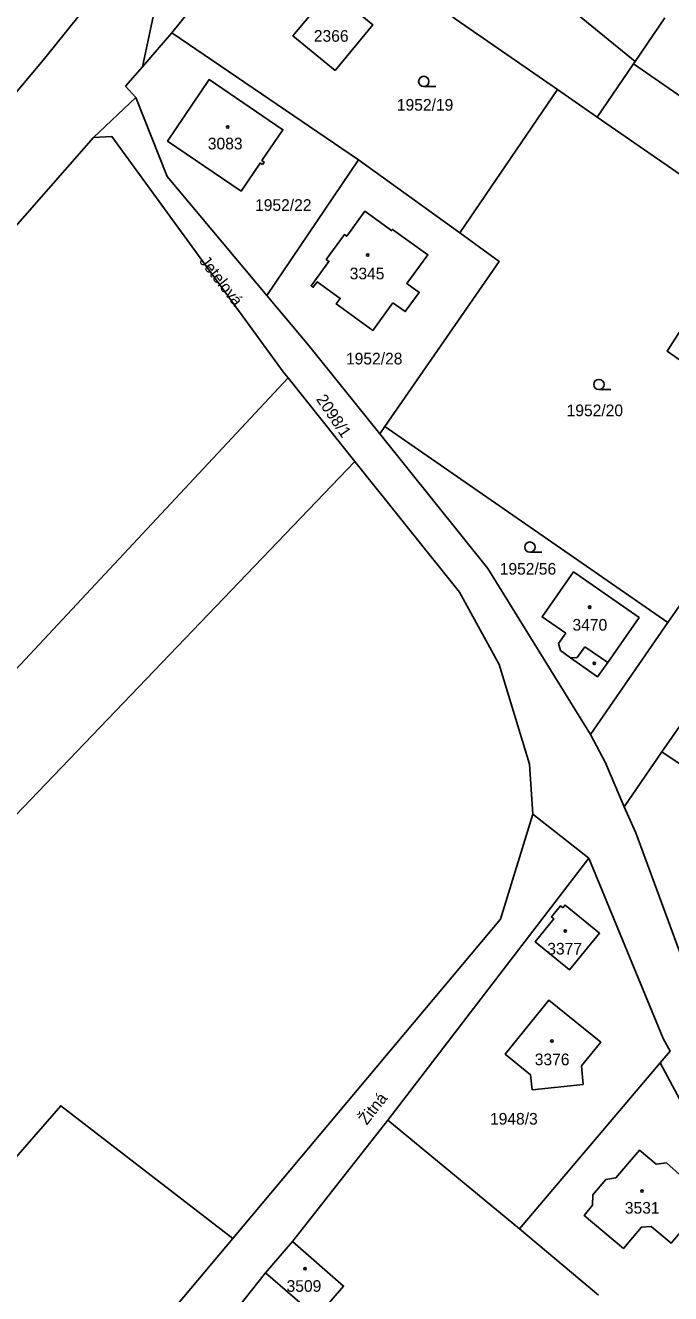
# Model space of a CAD drawing. Extents: x -679220 to -673243, y -1075091 to -1066557.
# Drawn here: x -676761.5 to -676667.6, y -1072885.5 to -1072700.8 of the extents above; entities that cross this region are included whole.
import ezdxf

# ---------------------------------------------------------------- set-up
doc = ezdxf.new("R2010")
doc.units = 0
for name, color, linetype in [('Hranice parcel', 7, 'Continuous'), ('Parcelní čísla', 7, 'Continuous'), ('Pop  PČ popisy', 7, 'Continuous'), ('Vnitřní kresba', 7, 'Continuous'), ('Značky budov', 7, 'Continuous'), ('Značky kultur', 7, 'Continuous')]:
    doc.layers.add(name, color=color, linetype=linetype)

msp = doc.modelspace()

# ---------------------------------------------------------------- linework, layer by layer
at = {"layer": 'Hranice parcel'}
for p, q in [((-676722.71, -1072680.24), (-676740.22, -1072701.84)), ((-676672.74, -1072706.03), (-676701.16, -1072682.79)), ((-676668.42, -1072699.67), (-676672.74, -1072706.03)), ((-676740.22, -1072701.84), (-676744.49, -1072706.81)), ((-676740.22, -1072701.84), (-676713, -1072720.34)), ((-676672.99, -1072706.39), (-676678.27, -1072714.14)), ((-676672.74, -1072706.03), (-676672.99, -1072706.39)), ((-676672.99, -1072706.39), (-676631.54, -1072735.13)), ((-676698.26, -1072731.01), (-676684.06, -1072710.13)), ((-676684.06, -1072710.13), (-676678.27, -1072714.14)), ((-676751.59, -1072717.1), (-676745.46, -1072711.26)), ((-676678.27, -1072714.14), (-676636.86, -1072742.81)), ((-676726.35, -1072740.11), (-676713, -1072720.34)), ((-676713, -1072720.34), (-676698.26, -1072731.01)), ((-676667.95, -1072787.75), (-676636.86, -1072742.81)), ((-676804.41, -1072838.99), (-676723.28, -1072752.14)), ((-676723.28, -1072752.14), (-676713.57, -1072764.29)), ((-676709.92, -1072760.26), (-676709.2, -1072759.21)), ((-676651.64, -1072781.8), (-676668.84, -1072806.61)), ((-676679.25, -1072804.07), (-676667.95, -1072787.75)), ((-676674.31, -1072814.63), (-676668.84, -1072806.61)), ((-676668.84, -1072806.61), (-676651.73, -1072818.21)), ((-676679.5, -1072822.07), (-676687.62, -1072815.67)), ((-676708.75, -1072860.26), (-676679.5, -1072822.07)), ((-676689.58, -1072876.08), (-676669.1, -1072851.93)), ((-676722.64, -1072877.92), (-676708.75, -1072860.26)), ((-676708.75, -1072860.26), (-676689.58, -1072876.08)), ((-676689.58, -1072876.08), (-676678.07, -1072885.77)), ((-676726.54, -1072882.5), (-676722.64, -1072877.92)), ((-676739.89, -1072899.25), (-676726.54, -1072882.5))]:
    msp.add_line(p, q, dxfattribs=at)
for points in [[(-676676.04, -1072600.97), (-676689.01, -1072617.2), (-676699.82, -1072629.74), (-676727.69, -1072660.82), (-676752.08, -1072697.33), (-676758.72, -1072705.55), (-676780.51, -1072731.52), (-676784.98, -1072736.24)], [(-676744.49, -1072706.81), (-676742.71, -1072698.63), (-676719.91, -1072671.69), (-676687.51, -1072637.46)], [(-676706.26, -1072693.79), (-676698.95, -1072699.81), (-676684.06, -1072710.13)], [(-676716.41, -1072707.37), (-676722.56, -1072702.31), (-676718.18, -1072697), (-676717.39, -1072697.65), (-676716.27, -1072696.3), (-676710.92, -1072700.7), (-676716.41, -1072707.37)], [(-676744.49, -1072706.81), (-676746.93, -1072709.65), (-676745.46, -1072711.26)], [(-676727, -1072721.06), (-676727.34, -1072720.83), (-676730.11, -1072724.92), (-676740.82, -1072717.63), (-676734.77, -1072708.67), (-676724.03, -1072715.97), (-676727.08, -1072720.48), (-676726.76, -1072720.7), (-676727, -1072721.06)], [(-676745.46, -1072711.26), (-676740.88, -1072722.79), (-676726.35, -1072740.11)], [(-676838.43, -1072808.67), (-676822.57, -1072792.43), (-676778.53, -1072747.78), (-676751.59, -1072717.1)], [(-676751.59, -1072717.1), (-676748.92, -1072716.97), (-676724, -1072751.24), (-676723.28, -1072752.14)], [(-676708.03, -1072741.17), (-676710.94, -1072745.2), (-676716.25, -1072741.35), (-676715.67, -1072740.54), (-676719.02, -1072738.11), (-676719.62, -1072738.93), (-676719.92, -1072738.71), (-676717.33, -1072735.15), (-676717.71, -1072734.87), (-676715.08, -1072731.25), (-676714.73, -1072731.5), (-676712.08, -1072727.86), (-676708.2, -1072730.66), (-676708.07, -1072730.49), (-676702.93, -1072734.19), (-676705.96, -1072738.39), (-676704.18, -1072739.67), (-676706.21, -1072742.48), (-676708.03, -1072741.17)], [(-676698.26, -1072731.01), (-676692.55, -1072735.15), (-676709.2, -1072759.21)], [(-676661.09, -1072737.1), (-676653.29, -1072742.44), (-676656.72, -1072747.46), (-676657.13, -1072747.18), (-676659.49, -1072750.66), (-676661.55, -1072749.26), (-676663.27, -1072751.6), (-676668.09, -1072748.23), (-676666.51, -1072745.81), (-676664.14, -1072742.34), (-676664.51, -1072742.09), (-676661.09, -1072737.1)], [(-676726.35, -1072740.11), (-676720.29, -1072747.34), (-676709.92, -1072760.26)], [(-676709.92, -1072760.26), (-676694.17, -1072779.89), (-676679.25, -1072804.07)], [(-676709.2, -1072759.21), (-676708.7, -1072759.55), (-676667.95, -1072787.75)], [(-676713.57, -1072764.29), (-676792.31, -1072846.42), (-676821.07, -1072880.72)], [(-676713.57, -1072764.29), (-676698.33, -1072783.34), (-676692.51, -1072793.87), (-676688.12, -1072808.39), (-676687.62, -1072815.67)], [(-676682.84, -1072789.3), (-676686.28, -1072786.94), (-676681.7, -1072780.38), (-676672.16, -1072787.04), (-676676.72, -1072793.59), (-676678.22, -1072795.7), (-676682.14, -1072792.91), (-676683.61, -1072791.82), (-676683.9, -1072790.82), (-676682.84, -1072789.3)], [(-676674.31, -1072814.63), (-676677.07, -1072808.2), (-676679.25, -1072804.07)], [(-676687.62, -1072815.67), (-676692.32, -1072830.97), (-676731.31, -1072877.48)], [(-676657.48, -1072854.68), (-676662.59, -1072845.67), (-676672.61, -1072818.42), (-676674.31, -1072814.63)], [(-676679.5, -1072822.07), (-676668.64, -1072848.35), (-676667.65, -1072850.23), (-676669.1, -1072851.93)], [(-676683.26, -1072829.33), (-676683.62, -1072829.04), (-676684.93, -1072830.65), (-676684.57, -1072830.94), (-676687.29, -1072834.28), (-676682.27, -1072838.36), (-676677.9, -1072833.02), (-676682.93, -1072828.93), (-676683.26, -1072829.33)], [(-676687.74, -1072855.83), (-676680.32, -1072855.06), (-676680.56, -1072852.36), (-676677.75, -1072848.88), (-676685.3, -1072842.77), (-676691.66, -1072850.67), (-676687.98, -1072853.65), (-676687.74, -1072855.83)], [(-676669.1, -1072851.93), (-676648.4, -1072890.46), (-676657.67, -1072902.92)], [(-676858.81, -1072994.55), (-676837.41, -1072957.76), (-676802.64, -1072911.26), (-676756.39, -1072858.15), (-676731.31, -1072877.48)], [(-676675.53, -1072868.64), (-676672.11, -1072864.65), (-676669.69, -1072866.66), (-676668.17, -1072866.46), (-676666.26, -1072868.17), (-676664.78, -1072866.45), (-676663.55, -1072867.5), (-676665.69, -1072869.99), (-676662.68, -1072872.49), (-676667.49, -1072878.19), (-676670.39, -1072875.75), (-676671.83, -1072875.84), (-676674.43, -1072878.94), (-676680.15, -1072874.17), (-676678.92, -1072872.66), (-676678.89, -1072871.16), (-676677.01, -1072868.92), (-676675.53, -1072868.64)], [(-676731.31, -1072877.48), (-676749.42, -1072899.07), (-676788.18, -1072949.54), (-676815.55, -1072992.76), (-676832.95, -1073032.45)], [(-676722.64, -1072877.92), (-676715.18, -1072884.43), (-676719.1, -1072888.96), (-676726.54, -1072882.5)]]:
    msp.add_lwpolyline(points, dxfattribs=at)
at = {"layer": 'Vnitřní kresba'}
for p, q in [((-676681.17, -1072792.84), (-676680.07, -1072791.31)), ((-676680.07, -1072791.31), (-676676.72, -1072793.59)), ((-676682.14, -1072792.91), (-676681.17, -1072792.84))]:
    msp.add_line(p, q, dxfattribs=at)
at = {"layer": 'Značky budov'}
for centre in [(-676732.07, -1072715.59), (-676711.68, -1072734.24), (-676679.35, -1072785.53), (-676678.69, -1072793.71), (-676682.91, -1072832.72), (-676684.86, -1072848.71), (-676671.72, -1072870.59), (-676720.8, -1072881.91)]:
    msp.add_circle(centre, 0.175, dxfattribs=at)
at = {"layer": 'Značky kultur'}
for p, q in [((-676703.51, -1072709.69), (-676701.76, -1072709.69)), ((-676678, -1072753.84), (-676676.25, -1072753.84)), ((-676688.05, -1072777.53), (-676686.3, -1072777.53))]:
    msp.add_line(p, q, dxfattribs=at)
for centre in [(-676703.51, -1072708.94), (-676678, -1072753.09), (-676688.05, -1072776.78)]:
    msp.add_circle(centre, 0.75, dxfattribs=at)

# ---------------------------------------------------------------- texts
at = {"layer": 'Parcelní čísla'}
for s, p in [('2366', (-676719.52, -1072703.16)), ('1952/19', (-676707.43, -1072713.2)), ('3083', (-676734.96, -1072718.84)), ('1952/22', (-676728.08, -1072727.8)), ('3345', (-676714.3, -1072737.77)), ('1952/28', (-676714.84, -1072750.17)), ('1952/20', (-676682.71, -1072757.71)), ('1952/56', (-676692.45, -1072780.79)), ('3470', (-676681.86, -1072788.95)), ('3377', (-676685.53, -1072836.13)), ('3376', (-676687.35, -1072852.26)), ('1948/3', (-676693.87, -1072860.91)), ('3531', (-676674.23, -1072873.88)), ('3509', (-676723.49, -1072885.27))]:
    msp.add_text(s, height=1.7, dxfattribs=at).set_placement(p)
msp.add_text('2098/1', height=1.7, rotation=304, dxfattribs=at).set_placement((-676719.26, -1072755.23))
at = {"layer": 'Pop  PČ popisy'}
for s, rotation, p in [('Jetelová', 308, (-676736.28, -1072735.16)), ('Žitná', 52, (-676711.82, -1072861.08))]:
    msp.add_text(s, height=1.7, rotation=rotation, dxfattribs=at).set_placement(p)

doc.saveas('drawing.dxf')
